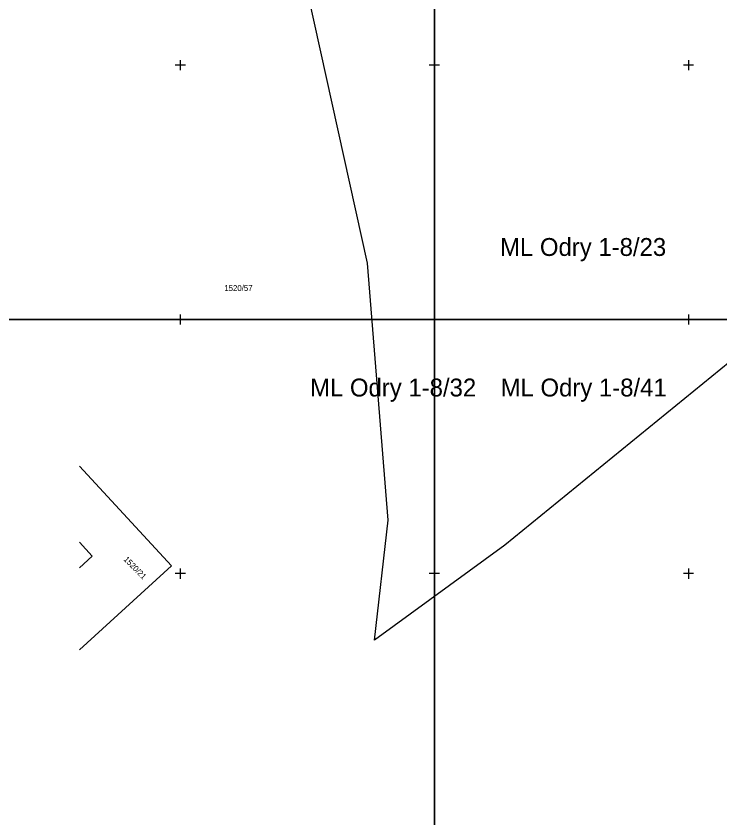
# Model space of a CAD drawing. Extents: x -504375 to -503125, y -1118000 to -1116474.
# Drawn here: x -503832.3 to -503693.8, y -1117098.1 to -1116940.3 of the extents above; entities that cross this region are included whole.
import ezdxf

# ---------------------------------------------------------------- set-up
doc = ezdxf.new("R2010")
doc.units = 0
for name, color, linetype in [('Podkladové mapy', 7, 'Continuous'), ('Síť dekadická', 7, 'Continuous'), ('Vrstva 34', 7, 'Continuous')]:
    doc.layers.add(name, color=color, linetype=linetype)

msp = doc.modelspace()

# ---------------------------------------------------------------- linework, layer by layer
at = {"layer": 'Podkladové mapy'}
for p, q in [((-503763.19, -1116988.95), (-503778.07, -1116921.42)), ((-503759.1, -1117039.48), (-503763.19, -1116988.95)), ((-503681.99, -1117000.24), (-503736.12, -1117044.39)), ((-503819.807, -1117028.867), (-503801.73, -1117048.49)), ((-503761.8, -1117063.11), (-503759.1, -1117039.48)), ((-503819.807, -1117043.821), (-503817.31, -1117046.55)), ((-503736.12, -1117044.39), (-503761.8, -1117063.11)), ((-503817.31, -1117046.55), (-503819.807, -1117048.853)), ((-503801.73, -1117048.49), (-503819.807, -1117064.979))]:
    msp.add_line(p, q, dxfattribs=at)
at = {"layer": 'Síť dekadická'}
for points in [[(-503750, -1116500), (-503750, -1117000), (-504375, -1117000), (-504375, -1116500)], [(-503125, -1116500), (-503125, -1117000), (-503750, -1117000), (-503750, -1116500)], [(-503750, -1117000), (-503750, -1117500), (-504375, -1117500), (-504375, -1117000)], [(-503125, -1117000), (-503125, -1117500), (-503750, -1117500), (-503750, -1117000)]]:
    msp.add_lwpolyline(points, close=True, dxfattribs=at)
at = {"layer": 'Vrstva 34'}
for p, q in [((-503799, -1116950), (-503801, -1116950)), ((-503800, -1116949), (-503800, -1116951)), ((-503749, -1116950), (-503751, -1116950)), ((-503750, -1116949), (-503750, -1116951)), ((-503699, -1116950), (-503701, -1116950)), ((-503700, -1116949), (-503700, -1116951)), ((-503800, -1116999), (-503800, -1117001)), ((-503750, -1116999), (-503750, -1117001)), ((-503700, -1116999), (-503700, -1117001)), ((-503799, -1117000), (-503801, -1117000)), ((-503749, -1117000), (-503751, -1117000)), ((-503699, -1117000), (-503701, -1117000)), ((-503800, -1117049), (-503800, -1117051)), ((-503750, -1117049), (-503750, -1117051)), ((-503700, -1117049), (-503700, -1117051)), ((-503799, -1117050), (-503801, -1117050)), ((-503749, -1117050), (-503751, -1117050)), ((-503699, -1117050), (-503701, -1117050))]:
    msp.add_line(p, q, dxfattribs=at)
for points in [[(-503750, -1116754.229), (-503750, -1117230.829)], [(-503819.807, -1117000), (-503275.634, -1117000)]]:
    msp.add_lwpolyline(points, dxfattribs=at)

# ---------------------------------------------------------------- texts
at = {"layer": 'Podkladové mapy'}
msp.add_text('1520/57', height=1.15, dxfattribs=at).set_placement((-503791.334, -1116994.404))
msp.add_text('1520/21', height=1.15, rotation=314.57178, dxfattribs=at).set_placement((-503811.24, -1117047.275))
at = {"layer": 'Vrstva 34'}
for s, p in [('ML Odry 1-8/23', (-503737.087, -1116987.513)), ('ML Odry 1-8/32', (-503774.463, -1117015.153)), ('ML Odry 1-8/41', (-503736.979, -1117015.153))]:
    msp.add_text(s, height=3.518, dxfattribs=at).set_placement(p)

doc.saveas('drawing.dxf')
